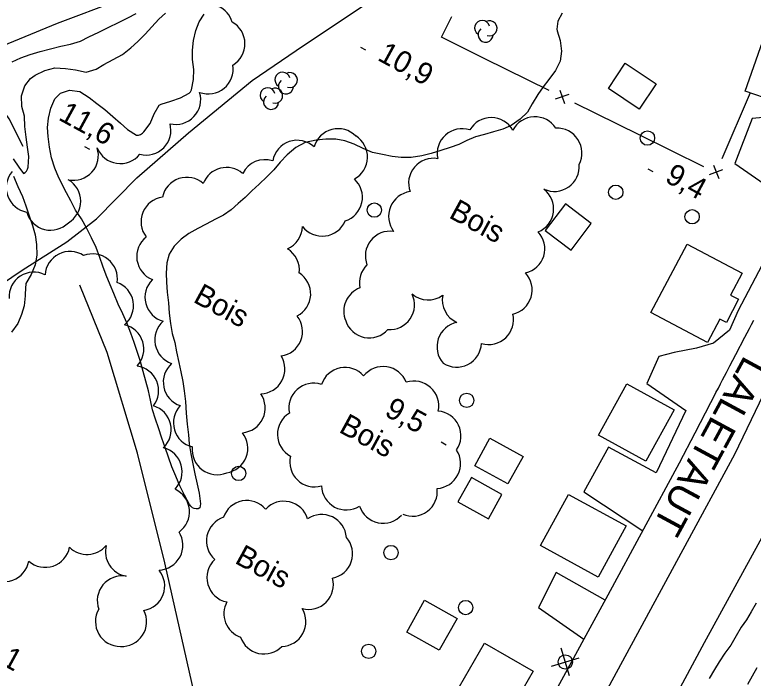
# Model space of a CAD drawing. Extents: x 219136 to 222520, y 5421589 to 5424530.
# Drawn here: x 221560.4 to 221663.2, y 5423227.8 to 5423320.3 of the extents above; entities that cross this region are included whole.
import ezdxf

# ---------------------------------------------------------------- set-up
doc = ezdxf.new("R2010")
doc.units = 0
for name, color, linetype in [('Level 1', 7, 'Continuous'), ('Level 19', 7, 'Continuous'), ('Level 2', 7, 'Continuous'), ('Level 21', 7, 'Continuous'), ('Level 22', 7, 'Continuous'), ('Level 3', 7, 'Continuous'), ('Level 31', 7, 'Continuous'), ('Level 36', 7, 'Continuous'), ('Level 37', 7, 'Continuous'), ('Level 4', 7, 'Continuous'), ('Level 44', 7, 'Continuous')]:
    doc.layers.add(name, color=color, linetype=linetype)

msp = doc.modelspace()

# ---------------------------------------------------------------- linework, layer by layer
at = {"layer": 'Level 1'}
for points in [[(221566.53, 5423297.53), (221565.93, 5423298.89), (221565.48, 5423300.35), (221565.19, 5423301.84), (221565.03, 5423303.29), (221564.95, 5423304.57), (221565.05, 5423305.85), (221565.38, 5423307.28), (221565.93, 5423308.55), (221566.72, 5423309.34), (221567.98, 5423309.78), (221569.44, 5423309.59), (221570.72, 5423308.74), (221571.78, 5423307.93), (221572.92, 5423307.06), (221574.04, 5423306.1), (221575.08, 5423305.18), (221576.07, 5423304.28), (221577.33, 5423303.51), (221577.62, 5423303.49), (221577.9, 5423303.57), (221578.16, 5423303.76), (221578.36, 5423303.95), (221579.22, 5423305.13), (221579.8, 5423306.47), (221580.5, 5423307.68), (221580.77, 5423307.8), (221582.13, 5423308.25), (221583.48, 5423308.7), (221584.67, 5423309.34), (221584.85, 5423309.55), (221585, 5423309.81), (221585.25, 5423311.27), (221585.3, 5423312.67), (221585.12, 5423314.03), (221585.13, 5423315.34), (221585.25, 5423316.67), (221585.61, 5423318.1), (221586.07, 5423319.29), (221586.76, 5423320.35)], [(221636.64, 5423320.49), (221636.04, 5423319.38), (221635.87, 5423318.29), (221635.95, 5423318.02), (221636.33, 5423316.71), (221636.55, 5423315.21), (221636.35, 5423313.8), (221635.71, 5423312.52), (221634.77, 5423311.27), (221634, 5423310.21), (221633.22, 5423309.15), (221632.46, 5423307.84), (221631.78, 5423306.69), (221630.8, 5423305.73), (221629.53, 5423304.85), (221628.37, 5423304.33), (221627.07, 5423303.97), (221625.79, 5423303.58), (221624.54, 5423303.27), (221623.36, 5423302.77), (221622.22, 5423302.2), (221621.03, 5423301.77), (221619.74, 5423301.37), (221618.39, 5423300.96), (221617.09, 5423300.61), (221615.6, 5423300.39), (221614.21, 5423300.4), (221612.94, 5423300.51), (221611.61, 5423300.82), (221610.22, 5423301.1), (221608.9, 5423301.64), (221607.67, 5423302.22), (221606.35, 5423302.71), (221605.1, 5423302.92), (221603.71, 5423302.93), (221602.34, 5423302.82), (221600.85, 5423302.46), (221599.52, 5423301.78), (221598.31, 5423300.77), (221597.33, 5423299.73), (221596.44, 5423298.67)], [(221596.44, 5423298.67), (221595.48, 5423297.67), (221594.4, 5423296.65), (221593.41, 5423295.72), (221592.48, 5423294.82), (221591.5, 5423293.98), (221590.5, 5423293.07), (221589.45, 5423292.35), (221588.32, 5423291.77), (221587.05, 5423291.11), (221585.86, 5423290.5), (221584.61, 5423289.79), (221583.55, 5423288.98), (221582.56, 5423288.03), (221581.9, 5423286.91), (221581.54, 5423285.71), (221581.46, 5423284.27), (221581.5, 5423283.01), (221581.62, 5423281.6), (221581.79, 5423280.1), (221581.86, 5423278.69), (221582.07, 5423277.26), (221582.32, 5423275.83), (221582.65, 5423274.57), (221582.92, 5423273.27), (221583.22, 5423271.81), (221583.5, 5423270.5), (221583.78, 5423269.14), (221583.98, 5423267.86), (221584.14, 5423266.35), (221584.24, 5423264.73), (221584.37, 5423263.19), (221584.55, 5423261.73), (221584.68, 5423260.46), (221584.92, 5423259.09), (221585.18, 5423257.66), (221585.44, 5423256.27), (221585.8, 5423254.85), (221586.07, 5423253.59), (221586.23, 5423252.1)], [(221560.2, 5423297.76), (221560.79, 5423296.32), (221561.43, 5423294.96), (221561.91, 5423293.63), (221562.36, 5423292.26), (221562.82, 5423290.9), (221563.22, 5423289.59), (221563.41, 5423288.26), (221563.43, 5423286.77), (221563.23, 5423285.43), (221562.64, 5423284.07), (221561.9, 5423282.81), (221561.84, 5423281.37), (221561.81, 5423281.1), (221561.69, 5423279.69), (221561.29, 5423278.51), (221560.8, 5423277.25), (221559.9, 5423276.05)], [(221586.23, 5423252.1), (221586.13, 5423251.56), (221585.9, 5423251.41), (221585.63, 5423251.38), (221585.36, 5423251.44), (221585.12, 5423251.56), (221584.88, 5423251.77), (221584.7, 5423252.02), (221584.02, 5423253.32), (221583.38, 5423254.63), (221582.83, 5423255.95), (221582.27, 5423257.26), (221581.8, 5423258.6), (221581.33, 5423259.94), (221580.88, 5423261.25), (221580.38, 5423262.7), (221579.96, 5423263.92), (221579.58, 5423265.19), (221579.26, 5423266.53), (221578.99, 5423267.86), (221578.65, 5423269.2), (221578.26, 5423270.57), (221577.82, 5423272.06), (221577.41, 5423273.35), (221577.01, 5423274.57), (221576.54, 5423275.91), (221576, 5423277.33), (221575.42, 5423278.57), (221574.76, 5423279.93), (221574.15, 5423281.4), (221573.65, 5423282.61), (221573.08, 5423284), (221572.64, 5423285.25), (221572.21, 5423286.44), (221571.73, 5423287.83), (221571.08, 5423289.18), (221570.41, 5423290.49), (221569.68, 5423291.83), (221568.83, 5423293.04), (221568.17, 5423294.32), (221567.58, 5423295.46), (221566.53, 5423297.53)]]:
    msp.add_lwpolyline(points, dxfattribs=at)
at = {"layer": 'Level 19'}
for points in [[(221675.79, 5423306.6), (221671.46, 5423306.38), (221665.66, 5423306.04), (221663.08, 5423305.84), (221660.69, 5423299.54), (221668.27, 5423294.27)], [(221659.93, 5423276.29), (221657.7, 5423274.51), (221655.35, 5423273.81), (221652.22, 5423273.2), (221650.08, 5423272.63), (221648.43, 5423268.87), (221653.85, 5423265.13)], [(221649.72, 5423256.42), (221643.08, 5423260.02), (221639.63, 5423253.76), (221647.85, 5423248.32)], [(221642.61, 5423238.65), (221635.79, 5423242.51), (221633.35, 5423237.66), (221639.67, 5423233.24)]]:
    msp.add_lwpolyline(points, dxfattribs=at)
at = {"layer": 'Level 2'}
for points in [[(221560.03, 5423313.71), (221561.23, 5423314.26), (221562.5, 5423314.76), (221563.9, 5423315.18), (221565.33, 5423315.54), (221566.81, 5423315.89), (221568.15, 5423316.18), (221569.51, 5423316.62), (221570.69, 5423317.18), (221572.08, 5423317.84), (221573.48, 5423318.53), (221574.81, 5423319.21), (221576.1, 5423319.87), (221577.27, 5423320.47)], [(221560.14, 5423300.21), (221560.95, 5423299.05), (221561.57, 5423298.16), (221561.82, 5423298.29), (221561.99, 5423298.48), (221562.14, 5423298.75), (221562.23, 5423299.01), (221562.31, 5423300.5), (221562.15, 5423301.82), (221561.94, 5423303.21), (221561.78, 5423304.68), (221561.74, 5423306.13), (221561.37, 5423307.49), (221561.29, 5423308.97), (221561.75, 5423310.35), (221562.58, 5423311.38), (221563.21, 5423311.88), (221564.58, 5423312.5), (221565.96, 5423312.86), (221567.44, 5423312.79), (221568.82, 5423312.58), (221570.31, 5423312.3), (221571.71, 5423312.71), (221572.8, 5423313.36), (221574.1, 5423314.05), (221575.4, 5423314.72), (221576.53, 5423315.65), (221577.5, 5423316.55), (221578.53, 5423317.57), (221579.48, 5423318.58), (221580.45, 5423319.67), (221581.37, 5423320.52)], [(221663.68, 5423238.25), (221662.96, 5423237.06), (221662.3, 5423235.93), (221661.56, 5423234.91), (221660.89, 5423233.69), (221660.12, 5423232.41), (221659.31, 5423231.28), (221658.5, 5423230.07), (221657.85, 5423228.99)], [(221657.85, 5423228.99), (221657.1, 5423227.74)], [(221663.73, 5423229.23), (221663.11, 5423228.07), (221662.47, 5423226.89)]]:
    msp.add_lwpolyline(points, dxfattribs=at)
at = {"layer": 'Level 21'}
for points in [[(221598.19, 5423127.91), (221604.53, 5423138.55), (221611.94, 5423151.53), (221620.58, 5423165.98), (221627.88, 5423179.66), (221634.15, 5423191.64), (221641.49, 5423204.6), (221649.09, 5423219.02), (221656.48, 5423232.78), (221670.64, 5423258.63), (221677.1, 5423271.47), (221682.35, 5423283.26), (221687.31, 5423296.06), (221690.46, 5423306.63), (221695.18, 5423319.42), (221699.72, 5423331.08), (221703.69, 5423341.19), (221705.26, 5423350.74), (221706.24, 5423361.14), (221704.65, 5423368.08), (221701.8, 5423372.21), (221699.74, 5423375.84), (221698.83, 5423377.61), (221698.8, 5423379.16)], [(221668.27, 5423294.27), (221667.01, 5423289.84), (221664.47, 5423285.32), (221661.13, 5423279.06), (221659.93, 5423276.29)], [(221653, 5423257.83), (221655.17, 5423262.02), (221657.34, 5423266.22), (221657.71, 5423266.94), (221658.06, 5423267.61), (221658.39, 5423268.24), (221658.7, 5423268.84), (221658.99, 5423269.39), (221659.53, 5423270.43), (221660, 5423271.34), (221660.84, 5423272.93), (221662.08, 5423275.32), (221662.71, 5423276.52), (221663.02, 5423277.11), (221663.33, 5423277.71)], [(221668.19, 5423274.75), (221668.07, 5423274.48), (221667.86, 5423274.04), (221667.68, 5423273.65), (221667.52, 5423273.32), (221667.24, 5423272.73), (221667.02, 5423272.28), (221666.71, 5423271.62), (221666.39, 5423270.96), (221663.52, 5423264.97), (221660.64, 5423258.98)], [(221653.85, 5423265.13), (221649.72, 5423256.42)], [(221660.64, 5423258.98), (221639.04, 5423219.11), (221616.62, 5423177.95), (221598.48, 5423145.47), (221572.5, 5423097.61), (221544.2, 5423045.77), (221525.59, 5423011.52), (221501.12, 5422966.85), (221480.22, 5422927.93), (221458.39, 5422888.43), (221441.16, 5422857.84), (221426.14, 5422830.08), (221397.61, 5422779.56)], [(221609.19, 5423176.93), (221620.62, 5423198.23), (221643.02, 5423239.4), (221653, 5423257.83)]]:
    msp.add_lwpolyline(points, dxfattribs=at)
at = {"layer": 'Level 22'}
msp.add_lwpolyline([(221505.9, 5423267.93), (221515.38, 5423269.03), (221527.3, 5423270.7), (221536.06, 5423271.25), (221544.82, 5423273.64), (221553, 5423279.01), (221561.4, 5423284.66), (221567.61, 5423288.64), (221571.74, 5423291.82), (221577.37, 5423297.54), (221584.58, 5423303.83), (221593.43, 5423311.13), (221600.6, 5423316), (221609.2, 5423321.71), (221615.82, 5423326.32), (221623.04, 5423330.4), (221627.93, 5423336.12), (221630.38, 5423340.36), (221632.1, 5423342.78), (221634.29, 5423345.1), (221635.78, 5423347.14), (221636.82, 5423349.27), (221637.71, 5423351.08), (221638.9, 5423352.17)], dxfattribs=at)
at = {"layer": 'Level 3'}
for p, q in [((221608.52, 5423315.78), (221609.22, 5423315.39)), ((221570.07, 5423301.93), (221570.77, 5423301.53)), ((221648.55, 5423298.82), (221649.25, 5423298.43)), ((221619.77, 5423260.73), (221620.48, 5423260.34))]:
    msp.add_line(p, q, dxfattribs=at)
at = {"layer": 'Level 31'}
for points in [[(221662.12, 5423309.63), (221665.48, 5423319.17), (221673.55, 5423316.33), (221672.6, 5423313.63), (221673.49, 5423313.32), (221672.29, 5423309.87), (221671.37, 5423310.19), (221670.2, 5423306.82)], [(221645.4, 5423313.51), (221649.72, 5423310.65), (221647.38, 5423307.12), (221643.07, 5423309.98)], [(221640.69, 5423291.19), (221637.08, 5423293.92), (221634.26, 5423290.2), (221637.87, 5423287.47)], [(221648.99, 5423278.76), (221654.04, 5423288.32), (221661.72, 5423284.26), (221660.1, 5423281.2), (221661.22, 5423280.61), (221659.51, 5423277.37), (221658.61, 5423277.85), (221656.89, 5423274.59)], [(221641.68, 5423261.67), (221645.62, 5423268.85), (221652.25, 5423265.22), (221648.31, 5423258.03)], [(221626.57, 5423261.24), (221631.18, 5423258.72), (221629.08, 5423254.87), (221624.47, 5423257.38)], [(221628.22, 5423253.4), (221623.98, 5423255.76), (221622.11, 5423252.39), (221626.35, 5423250.03)], [(221645.54, 5423249.01), (221641.64, 5423241.89), (221633.61, 5423246.28), (221637.52, 5423253.41)], [(221621.98, 5423236.13), (221619.51, 5423231.69), (221614.97, 5423234.2), (221617.43, 5423238.65)], [(221618.14, 5423219.39), (221625.79, 5423232.67), (221632.59, 5423228.75), (221624.93, 5423215.46)]]:
    msp.add_lwpolyline(points, close=True, dxfattribs=at)
at = {"layer": 'Level 36'}
for p, q in [((221637.63, 5423228.13), (221636.5, 5423231.96)), ((221635.15, 5423229.48), (221638.98, 5423230.61))]:
    msp.add_line(p, q, dxfattribs=at)
for centre in [(221648.51, 5423303.09), (221644.1, 5423295.54), (221610.47, 5423293.05), (221654.74, 5423292.12), (221623.33, 5423266.52), (221591.56, 5423256.34), (221612.78, 5423245.3), (221623.18, 5423237.64), (221609.68, 5423231.54), (221637.07, 5423230.05)]:
    msp.add_circle(centre, 1, dxfattribs=at)
at = {"layer": 'Level 37'}
for p, q in [((221636.3, 5423309.79), (221636.94, 5423307.89)), ((221637.57, 5423309.16), (221635.67, 5423308.52)), ((221657.71, 5423299.29), (221658.45, 5423297.43)), ((221657.15, 5423297.99), (221659.01, 5423298.73))]:
    msp.add_line(p, q, dxfattribs=at)
for points in [[(221625.86, 5423314.15), (221619.81, 5423317.14), (221621.28, 5423320.04)], [(221634.83, 5423309.72), (221625.86, 5423314.15)], [(221662.84, 5423309.38), (221658.88, 5423300.2)], [(221647.38, 5423303.52), (221638.41, 5423307.95)], [(221656.35, 5423299.1), (221647.38, 5423303.52)]]:
    msp.add_lwpolyline(points, dxfattribs=at)
at = {"layer": 'Level 4'}
for points in [[(221554.39, 5423314.28), (221556.5, 5423315.08), (221566.31, 5423319.1), (221574.72, 5423322.29), (221585.22, 5423327.43), (221592.58, 5423332.89), (221606.31, 5423341.67), (221616.43, 5423348.8), (221624.97, 5423354.26), (221637.36, 5423362.04), (221645.96, 5423367.59), (221654.33, 5423371.9), (221659.06, 5423374.32), (221662.66, 5423376.17), (221662.91, 5423376.27)], [(221561.52, 5423301.93), (221559.57, 5423305.77), (221556.97, 5423309.44), (221555.15, 5423312.69), (221554.39, 5423314.28)], [(221590.79, 5423209.71), (221585.36, 5423225.73), (221581.29, 5423243.86), (221577.47, 5423259.16), (221573.24, 5423273.2), (221569.43, 5423282.58)]]:
    msp.add_lwpolyline(points, dxfattribs=at)
at = {"layer": 'Level 44'}
for centre, radius, start, end in [((221587.34, 5423318.29), 3.46, 16.2858, 65.8251), ((221588.98, 5423316.24), 3.46, 300.9238, 60.9238), ((221625.48, 5423318.44), 1.05, 14.2713, 236.9557), ((221626.52, 5423318.39), 1.05, 251.4498, 117.1384), ((221625.96, 5423317.51), 1.05, 129.6037, 357.0607), ((221587.34, 5423312.7), 3.46, 249.4679, 9.4679), ((221597.67, 5423311.22), 1.05, 14.2713, 236.9557), ((221598.71, 5423311.17), 1.05, 251.4498, 117.1384), ((221598.15, 5423310.29), 1.05, 129.6037, 357.0607), ((221595.6, 5423309.06), 1.05, 14.2713, 236.9557), ((221596.64, 5423309.01), 1.05, 251.4498, 117.1384), ((221582.81, 5423308.46), 3.46, 256.5638, 16.5638), ((221596.08, 5423308.13), 1.05, 129.6037, 357.0607), ((221626.75, 5423302.48), 3.46, 29.5854, 149.5854), ((221632.84, 5423302.6), 3.46, 32.6245, 152.6245), ((221578.66, 5423304.18), 3.46, 255.354, 15.354), ((221605.42, 5423300.94), 3.46, 44.7372, 164.7372), ((221622.68, 5423300.94), 3.46, 71.9192, 191.9192), ((221635.92, 5423301.01), 3.46, 332.7323, 92.7323), ((221606.05, 5423300.44), 3.46, 298.1429, 58.1429), ((221599.72, 5423299.32), 3.46, 47.0205, 170.2007), ((221568.56, 5423300.67), 3.46, 257.8575, 17.8575), ((221575.08, 5423302.99), 3.46, 201.3466, 321.3466), ((221618.7, 5423296.81), 3.46, 80.0518, 200.0518), ((221595.22, 5423296.62), 3.46, 71.8763, 153.5488), ((221635.55, 5423299.11), 3.46, 245.0957, 5.0957), ((221562.64, 5423296.17), 3.46, 139.7296, 259.7296), ((221589.87, 5423295.53), 3.46, 49.4795, 159.2273), ((221566.1, 5423294.28), 3.46, 300.1079, 60.1079), ((221584.34, 5423294.16), 3.46, 48.499, 168.499), ((221605.35, 5423294.83), 3.46, 287.6407, 47.6407), ((221615.9, 5423292.19), 3.46, 97.5365, 217.5365), ((221631.98, 5423293.22), 3.46, 292.4109, 52.4109), ((221581.42, 5423291.42), 3.46, 97.8327, 217.8327), ((221565.36, 5423293.7), 3.46, 195.6715, 315.6715), ((221603.21, 5423292.87), 3.46, 217.2208, 337.2208), ((221596.99, 5423290.83), 3.46, 293.3045, 358.9762), ((221612.67, 5423286.65), 3.46, 82.0458, 200.8796), ((221630.76, 5423287.66), 3.46, 282.9297, 42.9297), ((221580.82, 5423286.58), 3.46, 128.2478, 248.2478), ((221568.04, 5423283.82), 3.46, 56.4455, 176.4455), ((221571.21, 5423283.48), 3.46, 351.3403, 111.3403), ((221596.57, 5423284.68), 3.46, 353.3045, 58.9762), ((221611.84, 5423282.92), 3.46, 133.9107, 192.1044), ((221563.03, 5423280.94), 3.46, 63.3796, 183.3796), ((221598.14, 5423281.37), 3.46, 297.2383, 57.2383), ((221628.99, 5423281.93), 3.46, 282.8142, 42.8142), ((221573.45, 5423279.71), 3.46, 309.9488, 69.9488), ((221581.97, 5423280.89), 3.46, 134.5053, 254.5053), ((221609.67, 5423278.95), 3.46, 110.5532, 202.8575), ((221612.6, 5423279.84), 3.46, 265.8601, 25.8601), ((221617.96, 5423283.99), 3.46, 229.6606, 305.6705), ((221623.39, 5423280.55), 3.46, 169.6606, 245.6705), ((221597, 5423276.14), 3.46, 278.2918, 38.2918), ((221609.76, 5423278.69), 3.46, 198.2474, 318.2474), ((221626.39, 5423277.76), 3.46, 253.245, 13.245), ((221574.89, 5423273.68), 3.46, 316.9023, 76.9023), ((221583.33, 5423274.95), 3.46, 131.3592, 251.3592), ((221622.65, 5423274), 3.46, 101.4656, 221.4656), ((221621.93, 5423274.62), 3.46, 237.1179, 357.1179), ((221594.55, 5423270.9), 3.46, 271.5414, 31.5414), ((221584.52, 5423269.07), 3.46, 131.5068, 251.5068), ((221576.95, 5423267.88), 3.46, 322.2329, 82.2329), ((221606.38, 5423267.65), 3.46, 41.4769, 161.4769), ((221611.68, 5423267.78), 3.46, 21.4027, 141.4027), ((221602.01, 5423265.46), 3.46, 71.8148, 191.8148), ((221615.98, 5423265.75), 3.46, 347.9754, 107.9754), ((221591.8, 5423265.46), 3.46, 274.8344, 34.8344), ((221578.71, 5423262.43), 3.46, 313.6293, 73.6293), ((221585.93, 5423263.4), 3.46, 136.2951, 256.2951), ((221600.43, 5423261.79), 3.46, 121.4623, 241.4623), ((221619.08, 5423261.58), 3.46, 325.1944, 85.1944), ((221589.38, 5423259.85), 3.46, 278.5589, 38.5589), ((221580.23, 5423256.57), 3.46, 315.5071, 75.5071), ((221588.54, 5423259.61), 3.46, 173.0231, 293.0231), ((221619.02, 5423257.7), 3.46, 273.296, 33.296), ((221602.14, 5423257.92), 3.46, 166.1089, 286.1089), ((221581.26, 5423250.99), 3.46, 305.319, 65.319), ((221606.56, 5423254.71), 3.46, 181.9862, 301.9862), ((221615.78, 5423253.83), 3.46, 246.762, 6.762), ((221592.71, 5423249.1), 3.46, 41.0036, 161.0036), ((221597.85, 5423249), 3.46, 16.7754, 136.7754), ((221611.69, 5423252.85), 3.46, 198.1377, 318.1377), ((221590.54, 5423246.94), 3.46, 108.5304, 228.5304), ((221603.13, 5423247.15), 3.46, 4.535, 124.535), ((221580.33, 5423246.32), 3.46, 272.2915, 32.2915), ((221603.98, 5423245.14), 3.46, 281.2279, 41.2279), ((221564.6, 5423246.7), 3.46, 228.977, 348.977), ((221570.43, 5423248.5), 3.46, 225.3983, 320.6543), ((221576.46, 5423245.43), 3.46, 165.3983, 260.6544), ((221558.92, 5423244.71), 3.46, 229.6635, 349.6635), ((221590.6, 5423241.81), 3.46, 132.9768, 258.3979), ((221577.8, 5423240.66), 3.46, 279.4275, 39.4275), ((221575.32, 5423238.6), 3.46, 80.2815, 200.2815), ((221601.31, 5423240.84), 3.46, 255.1098, 15.1098), ((221592.96, 5423236.78), 3.46, 151.7708, 250.7561), ((221597.47, 5423235.67), 3.46, 271.6841, 31.6841), ((221575.07, 5423235.68), 3.46, 150.1846, 270.1846), ((221575.27, 5423235.67), 3.46, 266.8875, 26.8875), ((221595.1, 5423234.63), 3.46, 198.846, 315.6207)]:
    msp.add_arc(centre, radius, start, end, dxfattribs=at)

# ---------------------------------------------------------------- texts
at = {"layer": 'Level 21'}
msp.add_text('LALETAUT', height=4, rotation=241.5493, dxfattribs=at).set_placement((221662.04, 5423272.93))
at = {"layer": 'Level 3'}
for s, p in [('10,9', (221610.76, 5423314.03)), ('11,6', (221566.31, 5423305.71)), ('9,4', (221650.79, 5423297.08)), ('9,5', (221611.73, 5423264.48)), ('9,1', (221555.46, 5423231.34))]:
    msp.add_text(s, height=3, rotation=331.383, dxfattribs=at).set_placement(p)
at = {"layer": 'Level 44'}
for p in [(221620.7, 5423292.07), (221585.08, 5423280.31), (221605.38, 5423262.17), (221590.87, 5423243.91)]:
    msp.add_text('Bois', height=3, rotation=331.3547, dxfattribs=at).set_placement(p)

doc.saveas('drawing.dxf')
